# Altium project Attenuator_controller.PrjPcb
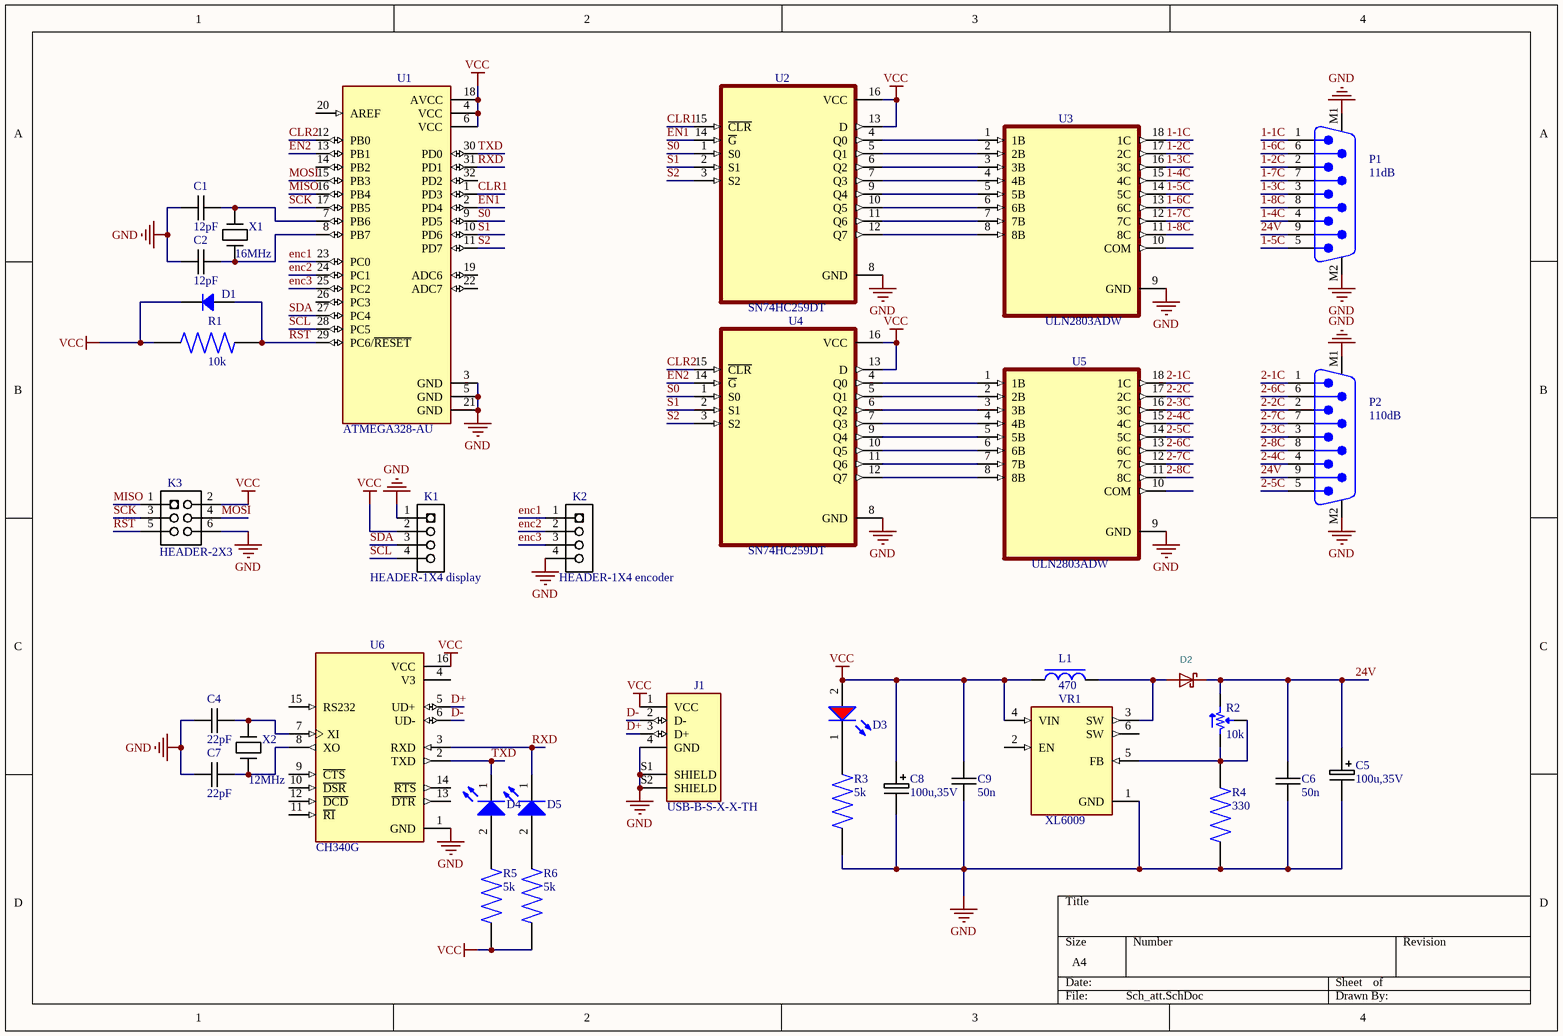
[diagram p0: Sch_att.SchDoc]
1 sheet, 35 parts. Net scope: global (net labels, ports and power ports of the same name join across sheets).
Board file: PCB_att.PcbDoc

## Sheet Sch_att.SchDoc
size A4; SheetNumber: 1; SheetTotal: 1; SPICEModelCacheRWTMKEKI: <root> / <DocumentId>RWTMKEKI</DocumentId> / <CacheFrame Number="0"> / <Model Name="1206_150120bs87000" Kind="CKT"> / <Text>****** / .subckt 1206_150120BS87000  1  2 / D1 1 2 SMCW / .MODEL SMCW D / + IS=27.217E-18 / + N=3.3922 / + RS=.54596 / + IKF=413.64E-6 / + CJO=1.0000E-12 / + M=.3333 / + VJ=.75 / + BV=5 / + IBV=100.00E-6 / + TT=5.0000E-9 / .ends</Text> / </Model> / <Model Name="1206_150120rs87000" Kind="CKT"> / <Text>****** / .subckt 1206_150120RS87000  1  2 / D1 1 2 SMCW / .MODEL SMCW D / + IS=8.3603E-18 / + N=2.1908 / + RS=1.0000E-6 / + IKF=.23331 / + CJO=1.0000E-12 / + M=.3333 / + VJ=.75 / + BV=5 / + IBV=100.00E-6 / + TT=5.0000E-9 / .ends</Text> / </Model> / </CacheFrame> / </root>

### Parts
C1  12pF  [1206C-GENERIC]
C2  12pF  [1206C-GENERIC]
C4  22pF  [1206C-GENERIC]
C5  100u,35V  [PANACAP-D-GENERIC]
C6  50n  [1206C-GENERIC]
C7  22pF  [1206C-GENERIC]
C8  100u,35V  [PANACAP-D-GENERIC]
C9  50n  [1206C-GENERIC]
D1  BAS83-GS08  [SOD-80 MiniMELF]  (value not drawn)
D2  Schottky-Diode  [DO-214AC_SMA]  (value not drawn)
D3  Red, 2V, 70°  [WL-SMCW_1206_150120xx87000]  (value not drawn)
D4  Blue, 3.2V, 70°  [WL-SMCW_1206_150120xx87000]  (value not drawn)
D5  Blue, 3.2V, 70°  [WL-SMCW_1206_150120xx87000]  (value not drawn)
J1  USB-B-S-X-X-TH  [SAMTEC_USB-B-S-X-X-TH]
K1  HEADER-1X4 display  [HEADER-1X4]
K2  HEADER-1X4 encoder  [HEADER-1X4]
K3  HEADER-2X3  [HEADER-2X3]
L1  470  [IHLP4040DZER220M5A]
P1  11dB  [618009231221]
P2  110dB  [618009231221]
R1  10k  [RESC3216X75N]
R2  10k  [BOURNS TRIMPOT 3296W]
R3  5k  [RESC3216X75N]
R4  330  [RESC3216X75N]
R5  5k  [RESC3216X75N]
R6  5k  [RESC3216X75N]
U1  ATMEGA328-AU  [QFP80P900X900X120-32N]
U2  SN74HC259DT  [SOIC127P600X175-16N]
U3  ULN2803ADW  [SOIC127P1030X265-18N]
U4  SN74HC259DT  [SOIC127P600X175-16N]
U5  ULN2803ADW  [SOIC127P1030X265-18N]
U6  CH340G  [SOIC127P600X180-16N]
VR1  XL6009  [DPAK170P1435X465-6N]
X1  16MHz  [XTAL-RU49/4]
X2  12MHz  [XTAL-RU49/4]

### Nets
GND: C1.1 C2.1 C4.1 C5.- C6.1 C7.1 C8.- C9.1 J1.4(GND) J1.S1(SHIELD) J1.S2(SHIELD) K1.1 K2.4 K3.6 P1.M1 P1.M2 P2.M1 P2.M2 R3.1 R4.1 U1.3(GND) U1.5(GND) U1.21(GND) U2.8(GND) U3.9(GND) U4.8(GND) U5.9(GND) U6.1(GND) VR1.1(GND)
VCC: C8.+ C9.2 D1.2 D3.2(A) J1.1(VCC) K1.2 K3.2 L1.1 R1.1 R5.1 R6.1 U1.4(VCC) U1.6(VCC) U1.18(AVCC) U2.13(D) U2.16(VCC) U4.13(D) U4.16(VCC) U6.16(VCC) VR1.4(VIN)
1-1C: P1.1 U3.18(1C)
1-2C: P1.2 U3.17(2C)
1-3C: P1.3 U3.16(3C)
1-4C: P1.4 U3.15(4C)
1-5C: P1.5 U3.14(5C)
1-6C: P1.6 U3.13(6C)
1-7C: P1.7 U3.12(7C)
1-8C: P1.8 U3.11(8C)
2-1C: P2.1 U5.18(1C)
2-2C: P2.2 U5.17(2C)
2-3C: P2.3 U5.16(3C)
2-4C: P2.4 U5.15(4C)
2-5C: P2.5 U5.14(5C)
2-6C: P2.6 U5.13(6C)
2-7C: P2.7 U5.12(7C)
2-8C: P2.8 U5.11(8C)
24V: C5.+ C6.2 D2.K P1.9 P2.9 R2.3
CLR1: U1.1(PD3) U2.15(~{CLR})
CLR2: U1.12(PB0) U4.15(~{CLR})
D+: J1.3(D+) U6.5(UD+)
D-: J1.2(D-) U6.6(UD-)
EN1: U1.2(PD4) U2.14(~{G})
EN2: U1.13(PB1) U4.14(~{G})
enc1: K2.1 U1.23(PC0)
enc2: K2.2 U1.24(PC1)
enc3: K2.3 U1.25(PC2)
MISO: K3.1 U1.16(PB4)
MOSI: K3.4 U1.15(PB3)
RST: D1.1 K3.5 R1.2 U1.29(PC6/~{RESET})
RXD: D5.1(K) U1.31(PD1) U6.3(RXD)
S0: U1.9(PD5) U2.1(S0) U4.1(S0)
S1: U1.10(PD6) U2.2(S1) U4.2(S1)
S2: U1.11(PD7) U2.3(S2) U4.3(S2)
SCK: K3.3 U1.17(PB5)
SCL: K1.4 U1.28(PC5)
SDA: K1.3 U1.27(PC4)
TXD: D4.1(K) U1.30(PD0) U6.2(TXD)
NetC1_2: C1.2 U1.7(PB6) X1.1
NetC2_2: C2.2 U1.8(PB7) X1.2
NetC4_2: C4.2 U6.7(XI) X2.1
NetC7_2: C7.2 U6.8(XO) X2.2
NetD2_A: D2.A L1.2 VR1.3(SW)
NetD3_1: D3.1(K) R3.2
NetD4_2: D4.2(A) R5.2
NetD5_2: D5.2(A) R6.2
NetR2_1: R2.1 R2.2 R4.2 VR1.5(FB)
NetU2_4: U2.4(Q0) U3.1(1B)
NetU2_5: U2.5(Q1) U3.2(2B)
NetU2_6: U2.6(Q2) U3.3(3B)
NetU2_7: U2.7(Q3) U3.4(4B)
NetU2_9: U2.9(Q4) U3.5(5B)
NetU2_10: U2.10(Q5) U3.6(6B)
NetU2_11: U2.11(Q6) U3.7(7B)
NetU2_12: U2.12(Q7) U3.8(8B)
NetU4_4: U4.4(Q0) U5.1(1B)
NetU4_5: U4.5(Q1) U5.2(2B)
NetU4_6: U4.6(Q2) U5.3(3B)
NetU4_7: U4.7(Q3) U5.4(4B)
NetU4_9: U4.9(Q4) U5.5(5B)
NetU4_10: U4.10(Q5) U5.6(6B)
NetU4_11: U4.11(Q6) U5.7(7B)
NetU4_12: U4.12(Q7) U5.8(8B)

Not connected (* = marked no-connect by the designer): U1 14(PB2) 19(ADC6) 20(AREF) 22(ADC7) 26(PC3) 32(PD2); U3 10(COM); U5 10(COM); U6 4(V3) 9(~{CTS}) 10(~{DSR}) 11(~{RI}) 12(~{DCD}) 13(~{DTR}) 14(~{RTS}) 15(RS232); VR1 2(EN) 6(SW)

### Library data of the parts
C1 C2 C4 C6 C7 C9 = 1206C-10U-35V-X7R: GENERIC CAPACITOR NON POLARISED 1206; Manufacturer Part Number: GMK316F106ZL-T; Manufacturer: Taiyo Yuden; Reel: C90
C5 C8 = PANACAP-100UF-16V-FK: GENERIC CAPACITOR POLARISED
D1 = BAS83-GS08: DIODE SCHOTTKY 60V 30MA SOD80; Manufacturer: Vishay Semiconductor Diodes Division; Capacitance @ Vr, F: 1.6pF @ 1V, 1MHz; Current - Average Rectified (Io): 30mA (DC); Current - Reverse Leakage @ Vr: 200nA @ 60V; Speed: Small Signal =< 200mA (Io), Any Speed; Voltage - Forward (Vf) (Max) @ If: 1V @ 15mA
D2 = Schottky-Diode: ki_description: Schottky Diode
D3 = 150120RS87000: WL-SMCW Mono-color Chip LED Waterclear, size 1206, Red, 2V, 70°; Manufacturer: Wurth Elektronik; Case/Size Code: 1206; Chip Technology: AlInGaP; Dominant Wavelength: 624nm; Luminous Intensity: 300mcd; Peak Wavelength: 632nm
D4 D5 = 150120BS87000: WL-SMCW Mono-color Chip LED Waterclear, size 1206, Blue, 3.2V, 70°; Manufacturer: Wurth Elektronik; Case/Size Code: 1206; Chip Technology: InGaN; Dominant Wavelength: 470nm; Luminous Intensity: 300mcd; Peak Wavelength: 465nm
J1 = USB-B-S-X-X-TH: USB-B (USB TYPE-B) USB 2.0 Receptacle Connector 4 Position Through Hole, Right Angle; MF: Samtec; MP: USB-B-S-F-W-TH-TR
K1 K2 = HEADER-1X4
L1 = IHLP4040DZER220M5A: 22 ÂµH Shielded Molded Inductor 4.1 A 75.44mOhm Max Nonstandard; MF: Vishay Dale
P1 P2 = 618009231221: WR-DSUB 8.08mm Male PCB Connector with Hex Screw, Angled, 9p; Manufacturer: Wurth Elektronik; Contact Resistance: 30mOhm; Rated Current: 3A; Working Voltage: 125VAC; Withstanding Voltage: 100VAC
R1 = CR1206-FX-4701ELF: RES 10K OHM 1/4W 1% 1206 SMD
R2 = 3296W-1-101RLF: TRIMMER 100 OHM 0.5W PC PIN TOP; Manufacturer: Bourns Inc.; Adjustment Type: Top Adjustment; Number of Turns: 25; Power (Watts): 0.5W, 1/2W; Resistance: 100 Ohms; Resistive Material: Cermet; Temperature Coefficient: ±100ppm/°C; Tolerance: ±10%; Value: 100 Ohms
R3-R6 = CR1206-FX-4701ELF: RES 5K OHM 1/4W 1% 1206 SMD
U1 = ATMEGA328-AU: AVR AVRÂ® ATmega Microcontroller IC 8-Bit 20MHz 32KB (16K x 16) FLASH 32-TQFP (7x7); MF: Microchip
U3 U5 = ULN2803ADW: 50-V, 8-ch darlington array; MF: Texas Instruments
U6 = CH340G: USB Interface Integrated Circuit; MF: WCH
VR1 = XL6009: The XL6009 regulator is a wide input range, current mode, DC/DC converter which is capable of generating either positive or negative output voltages.; MF: XLSEMI
X1 X2 = CRYSTAL-GENERIC: GENERIC CRYSTAL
